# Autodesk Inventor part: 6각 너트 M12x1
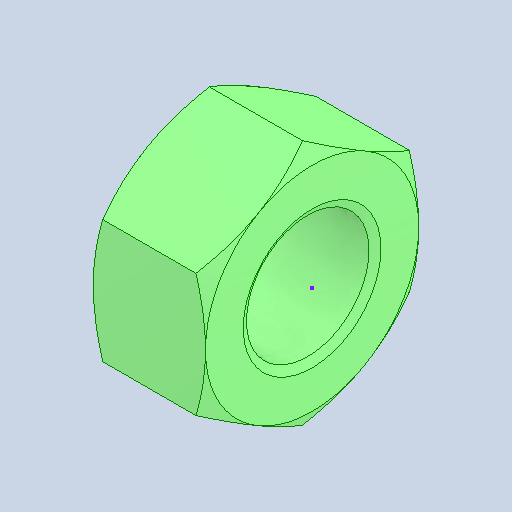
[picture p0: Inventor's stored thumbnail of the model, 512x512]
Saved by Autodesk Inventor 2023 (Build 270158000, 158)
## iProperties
Created: 2025-04
Part Number: 6각 너트 M12x1
Material: 강철, 연강
Description: 6각 너트
Document SubType Name: Modeling
Designer: User
Density: 7.85 g/cm^3
Appearance: 기본값
Author: jhkim
Sending System: Autodesk Inventor 2026
Preprocessor: ST-DEVELOPER v20.1
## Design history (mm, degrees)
node "복구된 형상1"
  node "스케치1"
feature "Solid1"
node "스케치3"
node "솔리드1"
